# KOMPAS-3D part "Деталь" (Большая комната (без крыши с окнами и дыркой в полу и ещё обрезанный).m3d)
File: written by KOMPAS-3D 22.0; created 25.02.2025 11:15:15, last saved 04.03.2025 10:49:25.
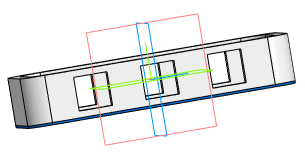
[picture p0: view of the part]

Document properties: Автор: Пользователь Windows; Полное имя файла: C:\Users\Student\Documents\Картошечка\База Сабнатика\Большая комната\Большая комната (без крыши с окнами и дыркой в полу и ещё обрезанный).m3d

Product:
- Part/product: Деталь
    Масса: 0.308955

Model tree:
1. Эскиз:1
2. Элемент выдавливания:1
     Расстояние 1 = 35
3. Скругление:2  (with: Элемент выдавливания:1)
     Радиус = 10
4. Скругление:1  (with: Элемент выдавливания:1)
     Радиус = 7
5. Эскиз:3  (with: Элемент выдавливания:1)
6. Элемент выдавливания:2
     Расстояние 2 = 7
7. Эскиз:4  (with: Элемент выдавливания:2)
8. Элемент выдавливания:3
     Расстояние 2 = 21
9. Эскиз:5  (with: Элемент выдавливания:1, Элемент выдавливания:2)
10. Элемент выдавливания:4
     Расстояние 2 = 70
11. Эскиз:8  (with: Элемент выдавливания:3)
12. Элемент выдавливания:7
     Расстояние 2 = 7
13. Эскиз:9  (with: Элемент выдавливания:1)
14. Элемент выдавливания:8
     Расстояние 2 = 6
